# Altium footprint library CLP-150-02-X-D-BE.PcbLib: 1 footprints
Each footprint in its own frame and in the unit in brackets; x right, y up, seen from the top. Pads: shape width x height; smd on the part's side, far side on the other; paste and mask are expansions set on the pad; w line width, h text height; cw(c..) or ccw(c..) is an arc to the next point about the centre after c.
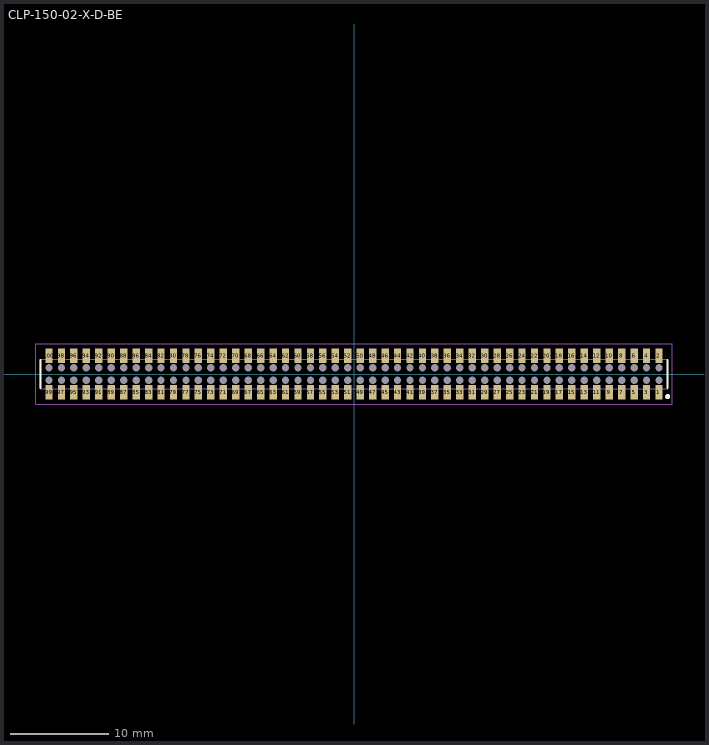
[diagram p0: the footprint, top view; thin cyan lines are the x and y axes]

## CLP-150-02-X-D-BE [mm] "1.27mm pitch, 100 pin, socket strip; low profile, vertical"
height 2.26
pads (200):
  rect 0.75x1.5 smd mask+0: 1(31.115,-1.87) 2(31.115,1.87) 3(29.845,-1.87) 4(29.845,1.87) 5(28.575,-1.87) 6(28.575,1.87) 7(27.305,-1.87) 8(27.305,1.87) 9(26.035,-1.87) 10(26.035,1.87) 11(24.765,-1.87) 12(24.765,1.87) 13(23.495,-1.87) 14(23.495,1.87) 15(22.225,-1.87) 16(22.225,1.87) 17(20.955,-1.87) 18(20.955,1.87) 19(19.685,-1.87) 20(19.685,1.87) 21(18.415,-1.87) 22(18.415,1.87) 23(17.145,-1.87) 24(17.145,1.87) 25(15.875,-1.87) 26(15.875,1.87) 27(14.605,-1.87) 28(14.605,1.87) 29(13.335,-1.87) 30(13.335,1.87) 31(12.065,-1.87) 32(12.065,1.87) 33(10.795,-1.87) 34(10.795,1.87) 35(9.525,-1.87) 36(9.525,1.87) 37(8.255,-1.87) 38(8.255,1.87) 39(6.985,-1.87) 40(6.985,1.87) 41(5.715,-1.87) 42(5.715,1.87) 43(4.445,-1.87) 44(4.445,1.87) 45(3.175,-1.87) 46(3.175,1.87) 47(1.905,-1.87) 48(1.905,1.87) 49(0.635,-1.87) 50(0.635,1.87) 51(-0.635,-1.87) 52(-0.635,1.87) 53(-1.905,-1.87) 54(-1.905,1.87) 55(-3.175,-1.87) 56(-3.175,1.87) 57(-4.445,-1.87) 58(-4.445,1.87) 59(-5.715,-1.87) 60(-5.715,1.87) 61(-6.985,-1.87) 62(-6.985,1.87) 63(-8.255,-1.87) 64(-8.255,1.87) 65(-9.525,-1.87) 66(-9.525,1.87) 67(-10.795,-1.87) 68(-10.795,1.87) 69(-12.065,-1.87) 70(-12.065,1.87) 71(-13.335,-1.87) 72(-13.335,1.87) 73(-14.605,-1.87) 74(-14.605,1.87) 75(-15.875,-1.87) 76(-15.875,1.87) 77(-17.145,-1.87) 78(-17.145,1.87) 79(-18.415,-1.87) 80(-18.415,1.87) 81(-19.685,-1.87) 82(-19.685,1.87) 83(-20.955,-1.87) 84(-20.955,1.87) 85(-22.225,-1.87) 86(-22.225,1.87) 87(-23.495,-1.87) 88(-23.495,1.87) 89(-24.765,-1.87) 90(-24.765,1.87) 91(-26.035,-1.87) 92(-26.035,1.87) 93(-27.305,-1.87) 94(-27.305,1.87) 95(-28.575,-1.87) 96(-28.575,1.87) 97(-29.845,-1.87) 98(-29.845,1.87) 99(-31.115,-1.87) 100(-31.115,1.87)
  round 0.5 hole 0.75 unplated mask+0: 101(-31.115,-0.635) 102(-31.115,0.635) 103(-29.845,-0.635) 104(-29.845,0.635) 105(-28.575,-0.635) 106(-28.575,0.635) 107(-27.305,-0.635) 108(-27.305,0.635) 109(-26.035,-0.635) 110(-26.035,0.635) 111(-24.765,-0.635) 112(-24.765,0.635) 113(-23.495,-0.635) 114(-23.495,0.635) 115(-22.225,-0.635) 116(-22.225,0.635) 117(-20.955,-0.635) 118(-20.955,0.635) 119(-19.685,-0.635) 120(-19.685,0.635) 121(-18.415,-0.635) 122(-18.415,0.635) 123(-17.145,-0.635) 124(-17.145,0.635) 125(-15.875,-0.635) 126(-15.875,0.635) 127(-14.605,-0.635) 128(-14.605,0.635) 129(-13.335,-0.635) 130(-13.335,0.635) 131(-12.065,-0.635) 132(-12.065,0.635) 133(-10.795,-0.635) 134(-10.795,0.635) 135(-9.525,-0.635) 136(-9.525,0.635) 137(-8.255,-0.635) 138(-8.255,0.635) 139(-6.985,-0.635) 140(-6.985,0.635) 141(-5.715,-0.635) 142(-5.715,0.635) 143(-4.445,-0.635) 144(-4.445,0.635) 145(-3.175,-0.635) 146(-3.175,0.635) 147(-1.905,-0.635) 148(-1.905,0.635) 149(-0.635,-0.635) 150(-0.635,0.635) 151(0.635,-0.635) 152(0.635,0.635) 153(1.905,-0.635) 154(1.905,0.635) 155(3.175,-0.635) 156(3.175,0.635) 157(4.445,-0.635) 158(4.445,0.635) 159(5.715,-0.635) 160(5.715,0.635) 161(6.985,-0.635) 162(6.985,0.635) 163(8.255,-0.635) 164(8.255,0.635) 165(9.525,-0.635) 166(9.525,0.635) 167(10.795,-0.635) 168(10.795,0.635) 169(12.065,-0.635) 170(12.065,0.635) 171(13.335,-0.635) 172(13.335,0.635) 173(14.605,-0.635) 174(14.605,0.635) 175(15.875,-0.635) 176(15.875,0.635) 177(17.145,-0.635) 178(17.145,0.635) 179(18.415,-0.635) 180(18.415,0.635) 181(19.685,-0.635) 182(19.685,0.635) 183(20.955,-0.635) 184(20.955,0.635) 185(22.225,-0.635) 186(22.225,0.635) 187(23.495,-0.635) 188(23.495,0.635) 189(24.765,-0.635) 190(24.765,0.635) 191(26.035,-0.635) 192(26.035,0.635) 193(27.305,-0.635) 194(27.305,0.635) 195(28.575,-0.635) 196(28.575,0.635) 197(29.845,-0.635) 198(29.845,0.635) 199(31.115,-0.635) 200(31.115,0.635)
Top Overlay:
  circle w0.25: c32,-2.3 r0.125
  lines w0.2: -32,-1.45 -32,1.45 ; 32,-1.45 32,1.45
Mechanical 12:
  lines w0.001: -32,-1.5 -32,1.5 32,1.5 32,-1.5 -32,-1.5
Mechanical 13:
  lines w0.1: -32,-1.5 -32,1.5 32,1.5 32,-1.5 -32,-1.5
  text ".Designator" at 0.254,0.254 h1.52
Mechanical 15:
  lines w0.05: -32.461,-3.099 -32.461,3.099 32.461,3.099 32.461,-3.099 -32.461,-3.099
